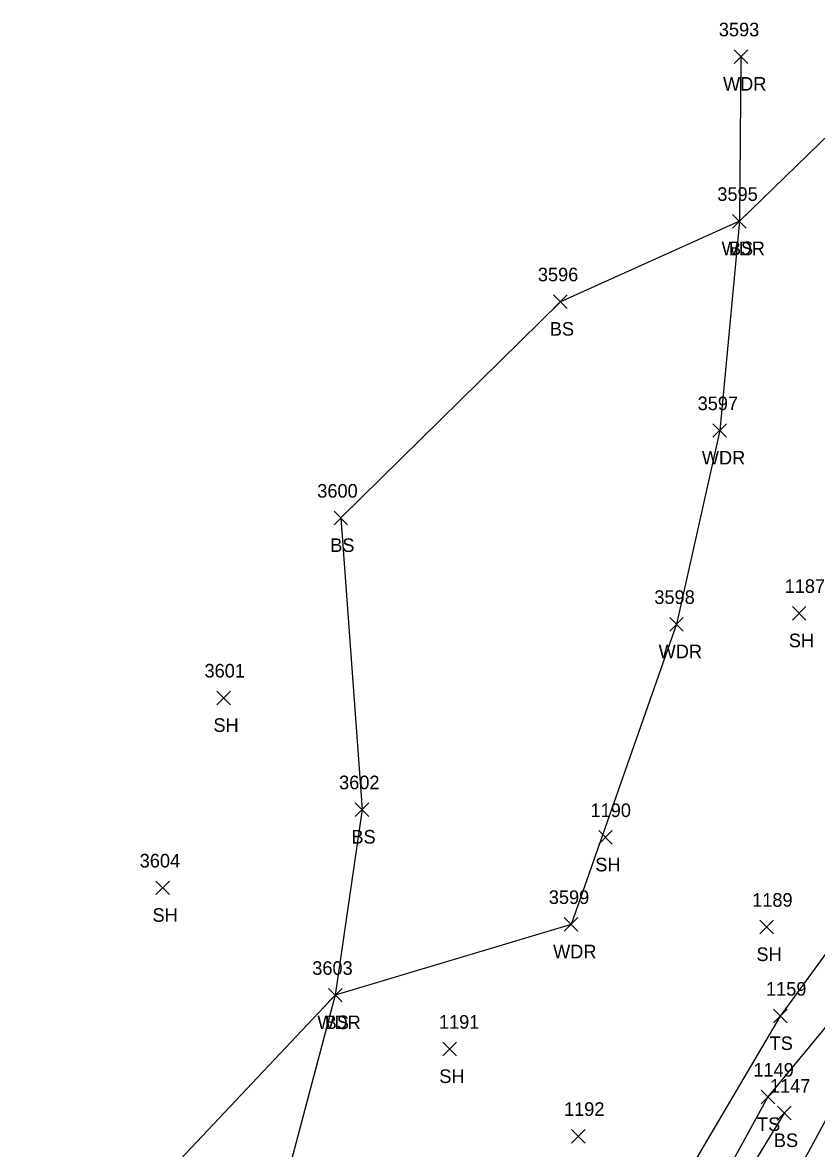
# Model space of a CAD drawing. Extents: x 1634209 to 1639641, y 608564 to 612258.
# Drawn here: x 1639356.8 to 1639473.7, y 612059.5 to 612225.3 of the extents above; entities that cross this region are included whole.
import ezdxf

# ---------------------------------------------------------------- set-up
doc = ezdxf.new("R2010")
doc.units = 0
for name, color, linetype in [('L_A', 7, 'Continuous'), ('L_I', 7, 'Continuous'), ('L_TIC', 7, 'Continuous'), ('LAWA', 7, 'Continuous'), ('LELB', 7, 'Continuous')]:
    doc.layers.add(name, color=color, linetype=linetype)

msp = doc.modelspace()

# ---------------------------------------------------------------- linework, layer by layer
at = {"layer": 'L_TIC'}
for points in [[(1639461.56, 612219.23), (1639463.56, 612221.23)], [(1639463.56, 612219.23), (1639461.56, 612221.23)], [(1639461.33, 612195), (1639463.33, 612197)], [(1639463.33, 612195), (1639461.33, 612197)], [(1639461.33, 612195), (1639463.33, 612197)], [(1639463.33, 612195), (1639461.33, 612197)], [(1639434.98, 612183.15), (1639436.98, 612185.15)], [(1639436.98, 612183.15), (1639434.98, 612185.15)], [(1639458.44, 612164.18), (1639460.44, 612166.18)], [(1639460.44, 612164.18), (1639458.44, 612166.18)], [(1639402.66, 612151.3), (1639404.66, 612153.3)], [(1639404.66, 612151.3), (1639402.66, 612153.3)], [(1639470.12, 612137.27), (1639472.12, 612139.27)], [(1639472.12, 612137.27), (1639470.12, 612139.27)], [(1639452.07, 612135.65), (1639454.07, 612137.65)], [(1639454.07, 612135.65), (1639452.07, 612137.65)], [(1639385.41, 612124.81), (1639387.41, 612126.81)], [(1639387.41, 612124.81), (1639385.41, 612126.81)], [(1639405.78, 612108.36), (1639407.78, 612110.36)], [(1639407.78, 612108.36), (1639405.78, 612110.36)], [(1639441.62, 612104.26), (1639443.62, 612106.26)], [(1639443.62, 612104.26), (1639441.62, 612106.26)], [(1639376.44, 612096.84), (1639378.44, 612098.84)], [(1639378.44, 612096.84), (1639376.44, 612098.84)], [(1639436.54, 612091.46), (1639438.54, 612093.46)], [(1639438.54, 612091.46), (1639436.54, 612093.46)], [(1639465.35, 612091.06), (1639467.35, 612093.06)], [(1639467.35, 612091.06), (1639465.35, 612093.06)], [(1639401.84, 612081.03), (1639403.84, 612083.03)], [(1639403.84, 612081.03), (1639401.84, 612083.03)], [(1639401.84, 612081.03), (1639403.84, 612083.03)], [(1639403.84, 612081.03), (1639401.84, 612083.03)], [(1639467.37, 612077.96), (1639469.37, 612079.96)], [(1639469.37, 612077.96), (1639467.37, 612079.96)], [(1639418.66, 612073.1), (1639420.66, 612075.1)], [(1639420.66, 612073.1), (1639418.66, 612075.1)], [(1639465.52, 612066.04), (1639467.52, 612068.04)], [(1639467.52, 612066.04), (1639465.52, 612068.04)], [(1639467.96, 612063.67), (1639469.96, 612065.67)], [(1639469.96, 612063.67), (1639467.96, 612065.67)], [(1639437.63, 612060.26), (1639439.63, 612062.26)], [(1639439.63, 612060.26), (1639437.63, 612062.26)]]:
    msp.add_lwpolyline(points, dxfattribs=at)
at = {"layer": 'LAWA'}
msp.add_lwpolyline([(1639462.56, 612220.23), (1639462.33, 612196), (1639459.44, 612165.18), (1639453.07, 612136.65), (1639437.54, 612092.46), (1639402.84, 612082.03), (1639374.32, 612051.81), (1639347.85, 612027.27), (1639335.09, 612005.49), (1639370.02, 611982.63)], dxfattribs=at)
at = {"layer": 'LELB'}
for points in [[(1639515.85, 612224.44), (1639477.4, 612210.66), (1639462.33, 612196), (1639435.98, 612184.15), (1639403.66, 612152.3), (1639406.78, 612109.36), (1639402.84, 612082.03), (1639389.56, 612032.06)], [(1639486.03, 612090.67), (1639466.52, 612067.04), (1639456.07, 612047.96), (1639446.25, 612030.94), (1639439.22, 612012.36), (1639431.5, 611996.97), (1639427.2, 611981.49), (1639430.09, 611997.28), (1639434.15, 612016.51), (1639442.18, 612035.71), (1639452.83, 612052.53), (1639468.37, 612078.96), (1639484.08, 612100.5), (1639508.75, 612130.39), (1639537.72, 612170.27), (1639559.87, 612201)], [(1639563.38, 612198.7), (1639539.24, 612164.06), (1639514.54, 612127.14), (1639495.77, 612095.8), (1639476.98, 612067.19), (1639457.71, 612031.74), (1639439.5, 611994.46), (1639424.36, 611955.72), (1639410.24, 611915.34), (1639396.62, 611874), (1639380.38, 611821.61)], [(1639433.79, 611996.15), (1639442.46, 612015.93), (1639454.06, 612040.2), (1639468.96, 612064.67)]]:
    msp.add_lwpolyline(points, dxfattribs=at)

# ---------------------------------------------------------------- texts
at = {"layer": 'L_A'}
for s, p in [('WDR', (1639459.92, 612215.23)), ('WDR', (1639459.7, 612191)), ('BS', (1639460.78, 612191)), ('BS', (1639434.42, 612179.15)), ('WDR', (1639456.8, 612160.18)), ('BS', (1639402.1, 612147.3)), ('SH', (1639469.6, 612133.27)), ('WDR', (1639450.44, 612131.65)), ('SH', (1639384.9, 612120.81)), ('BS', (1639405.22, 612104.36)), ('SH', (1639441.11, 612100.26)), ('SH', (1639375.93, 612092.84)), ('WDR', (1639434.9, 612087.46)), ('SH', (1639464.84, 612087.06)), ('WDR', (1639400.2, 612077.03)), ('BS', (1639401.28, 612077.03)), ('TS', (1639466.78, 612073.96)), ('SH', (1639418.15, 612069.1)), ('TS', (1639464.93, 612062.04)), ('BS', (1639467.4, 612059.67))]:
    msp.add_text(s, height=2, dxfattribs=at).set_placement(p)
at = {"layer": 'L_I'}
for s, p in [('3593', (1639459.3, 612223.23)), ('3595', (1639459.08, 612199)), ('3595', (1639459.08, 612199)), ('3596', (1639432.66, 612187.15)), ('3597', (1639456.18, 612168.18)), ('3600', (1639400.19, 612155.3)), ('1187', (1639468.99, 612141.27)), ('3598', (1639449.81, 612139.65)), ('3601', (1639383.59, 612128.81)), ('3602', (1639403.4, 612112.36)), ('1190', (1639440.41, 612108.26)), ('3604', (1639374.05, 612100.84)), ('3599', (1639434.27, 612095.46)), ('1189', (1639464.21, 612095.06)), ('3603', (1639399.45, 612085.03)), ('3603', (1639399.45, 612085.03)), ('1159', (1639466.24, 612081.96)), ('1191', (1639418.1, 612077.1)), ('1149', (1639464.38, 612070.04)), ('1147', (1639466.83, 612067.67)), ('1192', (1639436.51, 612064.26))]:
    msp.add_text(s, height=2, dxfattribs=at).set_placement(p)

doc.saveas('drawing.dxf')
